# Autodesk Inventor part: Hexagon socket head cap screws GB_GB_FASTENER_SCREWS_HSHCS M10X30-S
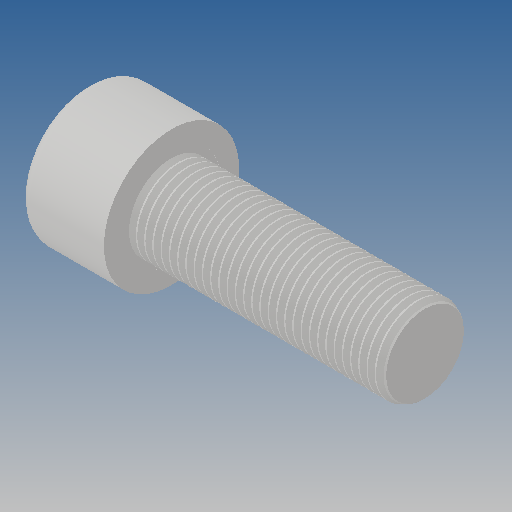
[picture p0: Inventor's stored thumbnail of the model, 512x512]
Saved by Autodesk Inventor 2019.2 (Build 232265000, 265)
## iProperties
Created: 2013-09
Part Number: Hexagon socket head cap screws GB_GB_FASTENER_SCREWS_HSHCS M10X30-S
Material: Ogólny
Document SubType Name: Modeling
Designer: CADENGINEERING4
Density: 1 g/cm^3
Appearance: Domyślna
Author: CADENGINEERING4
Revision Number: ÈÎºÎ
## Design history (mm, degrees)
feature "LPattern10"
node "Bryła1"
